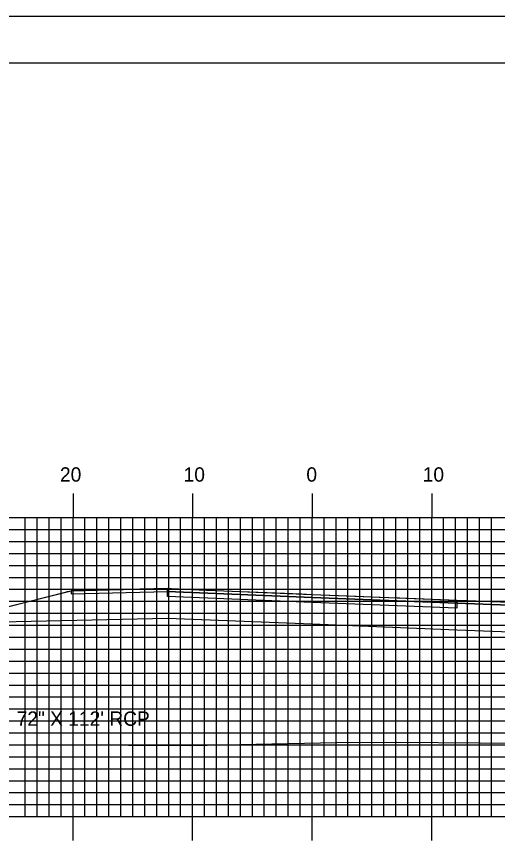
# Model space of a CAD drawing. Extents: x 1814915 to 1815259, y 442591 to 442811.
# Drawn here: x 1815056.3 to 1815096.5, y 442741.2 to 442810.5 of the extents above; entities that cross this region are included whole.
import ezdxf

# ---------------------------------------------------------------- set-up
doc = ezdxf.new("R2010")
doc.units = 0
for name, color, linetype in [('BORDER', 7, 'Continuous'), ('D_Drainage_Culvert', 7, 'Continuous'), ('D_Drainage_Text', 7, 'Continuous'), ('D_Roadway_Centerline', 7, 'Continuous'), ('D_Roadway_Edge_Shoulder', 7, 'Continuous'), ('D_Roadway_Edge_TW', 7, 'Continuous'), ('D_Roadway_Pavement', 7, 'Continuous'), ('D_Roadway_SubGrade', 7, 'Continuous'), ('H_V ANNOTATION', 7, 'Continuous'), ('MAJOR', 7, 'Continuous'), ('MINOR', 7, 'Continuous'), ('PLOT BOUNDARY', 7, 'Continuous'), ('S_Roadway_Centerline', 7, 'Continuous')]:
    doc.layers.add(name, color=color, linetype=linetype)

msp = doc.modelspace()

# ---------------------------------------------------------------- linework, layer by layer
at = {"layer": 'BORDER'}
msp.add_lwpolyline([(1814931.421, 442596.665), (1815251.421, 442596.665), (1815251.421, 442806.665), (1814931.421, 442806.665)], close=True, dxfattribs=at)
at = {"layer": 'D_Drainage_Culvert'}
for p, q in [((1815023.546, 442754.665), (1815135.546, 442754.665)), ((1815023.546, 442748.665), (1815135.546, 442748.665))]:
    msp.add_line(p, q, dxfattribs=at)
at = {"layer": 'D_Roadway_Centerline'}
msp.add_lwpolyline([(1815055.775, 442761.27), (1815057.309, 442761.655), (1815060.475, 442762.45), (1815060.571, 442762.475), (1815060.867, 442762.549), (1815063.058, 442762.599), (1815064.017, 442762.621), (1815068.928, 442762.734), (1815069.264, 442762.72), (1815071.561, 442762.625), (1815072.196, 442762.599), (1815075.06, 442762.482), (1815077.982, 442762.364), (1815080.142, 442762.277), (1815080.312, 442762.27), (1815080.556, 442762.26), (1815081.021, 442762.242), (1815084.712, 442762.094), (1815086.628, 442762.019), (1815087.446, 442761.986), (1815088.366, 442761.95), (1815093.114, 442761.764), (1815096.36, 442761.639), (1815101.177, 442761.455)], dxfattribs=at)
at = {"layer": 'D_Roadway_Edge_Shoulder'}
for points in [[(1815068.928, 442762.734), (1815060.867, 442762.549), (1815060.867, 442762.299), (1815068.928, 442762.484)], [(1815093.114, 442761.764), (1815101.177, 442761.455), (1815101.177, 442761.205), (1815093.114, 442761.514)]]:
    msp.add_lwpolyline(points, close=True, dxfattribs=at)
at = {"layer": 'D_Roadway_Edge_TW'}
msp.add_lwpolyline([(1815068.928, 442762.484), (1815068.928, 442762.734), (1815081.021, 442762.242), (1815093.114, 442761.764), (1815093.114, 442761.514), (1815081.021, 442761.992)], close=True, dxfattribs=at)
at = {"layer": 'D_Roadway_Pavement'}
msp.add_lwpolyline([(1815068.928, 442762.067), (1815068.928, 442762.484), (1815081.021, 442761.992), (1815093.114, 442761.514), (1815093.114, 442761.098), (1815081.021, 442761.575)], close=True, dxfattribs=at)
at = {"layer": 'D_Roadway_SubGrade'}
msp.add_lwpolyline([(1815068.928, 442760.234), (1815049.915, 442759.798), (1815060.867, 442762.549), (1815060.867, 442762.299), (1815068.928, 442762.484), (1815081.021, 442761.992), (1815093.114, 442761.514), (1815101.177, 442761.205), (1815101.177, 442761.455), (1815113.323, 442758.5), (1815093.114, 442759.264), (1815081.021, 442759.742)], close=True, dxfattribs=at)
at = {"layer": 'MAJOR'}
for p, q in [((1815061.021, 442770.669), (1815061.021, 442768.665)), ((1815071.021, 442770.669), (1815071.021, 442768.665)), ((1815081.021, 442770.669), (1815081.021, 442768.665)), ((1815091.021, 442770.669), (1815091.021, 442768.665)), ((1814941.021, 442768.665), (1815221.021, 442768.665)), ((1814941.021, 442768.665), (1815221.021, 442768.665)), ((1815061.021, 442743.665), (1815061.021, 442768.665)), ((1815071.021, 442743.665), (1815071.021, 442768.665)), ((1815081.021, 442743.665), (1815081.021, 442768.665)), ((1815091.021, 442743.665), (1815091.021, 442768.665)), ((1814941.021, 442763.665), (1815221.021, 442763.665)), ((1814941.021, 442758.665), (1815221.021, 442758.665)), ((1814941.021, 442753.665), (1815221.021, 442753.665)), ((1814941.021, 442748.665), (1815221.021, 442748.665)), ((1814941.021, 442743.665), (1815221.021, 442743.665)), ((1814941.021, 442743.665), (1815221.021, 442743.665)), ((1815061.021, 442741.661), (1815061.021, 442743.665)), ((1815071.021, 442741.661), (1815071.021, 442743.665)), ((1815081.021, 442741.661), (1815081.021, 442743.665)), ((1815091.021, 442741.661), (1815091.021, 442743.665))]:
    msp.add_line(p, q, dxfattribs=at)
at = {"layer": 'MINOR'}
for p, q in [((1815057.021, 442743.665), (1815057.021, 442768.665)), ((1815058.021, 442743.665), (1815058.021, 442768.665)), ((1815059.021, 442743.665), (1815059.021, 442768.665)), ((1815060.021, 442743.665), (1815060.021, 442768.665)), ((1815062.021, 442743.665), (1815062.021, 442768.665)), ((1815063.021, 442743.665), (1815063.021, 442768.665)), ((1815064.021, 442743.665), (1815064.021, 442768.665)), ((1815065.021, 442743.665), (1815065.021, 442768.665)), ((1815066.021, 442743.665), (1815066.021, 442768.665)), ((1815067.021, 442743.665), (1815067.021, 442768.665)), ((1815068.021, 442743.665), (1815068.021, 442768.665)), ((1815069.021, 442743.665), (1815069.021, 442768.665)), ((1815070.021, 442743.665), (1815070.021, 442768.665)), ((1815072.021, 442743.665), (1815072.021, 442768.665)), ((1815073.021, 442743.665), (1815073.021, 442768.665)), ((1815074.021, 442743.665), (1815074.021, 442768.665)), ((1815075.021, 442743.665), (1815075.021, 442768.665)), ((1815076.021, 442743.665), (1815076.021, 442768.665)), ((1815077.021, 442743.665), (1815077.021, 442768.665)), ((1815078.021, 442743.665), (1815078.021, 442768.665)), ((1815079.021, 442743.665), (1815079.021, 442768.665)), ((1815080.021, 442743.665), (1815080.021, 442768.665)), ((1815082.021, 442743.665), (1815082.021, 442768.665)), ((1815083.021, 442743.665), (1815083.021, 442768.665)), ((1815084.021, 442743.665), (1815084.021, 442768.665)), ((1815085.021, 442743.665), (1815085.021, 442768.665)), ((1815086.021, 442743.665), (1815086.021, 442768.665)), ((1815087.021, 442743.665), (1815087.021, 442768.665)), ((1815088.021, 442743.665), (1815088.021, 442768.665)), ((1815089.021, 442743.665), (1815089.021, 442768.665)), ((1815090.021, 442743.665), (1815090.021, 442768.665)), ((1815092.021, 442743.665), (1815092.021, 442768.665)), ((1815093.021, 442743.665), (1815093.021, 442768.665)), ((1815094.021, 442743.665), (1815094.021, 442768.665)), ((1815095.021, 442743.665), (1815095.021, 442768.665)), ((1815096.021, 442743.665), (1815096.021, 442768.665)), ((1814941.021, 442767.665), (1815221.021, 442767.665)), ((1814941.021, 442766.665), (1815221.021, 442766.665)), ((1814941.021, 442765.665), (1815221.021, 442765.665)), ((1814941.021, 442764.665), (1815221.021, 442764.665)), ((1814941.021, 442762.665), (1815221.021, 442762.665)), ((1814941.021, 442761.665), (1815221.021, 442761.665)), ((1814941.021, 442760.665), (1815221.021, 442760.665)), ((1814941.021, 442759.665), (1815221.021, 442759.665)), ((1814941.021, 442757.665), (1815221.021, 442757.665)), ((1814941.021, 442756.665), (1815221.021, 442756.665)), ((1814941.021, 442755.665), (1815221.021, 442755.665)), ((1814941.021, 442754.665), (1815221.021, 442754.665)), ((1814941.021, 442752.665), (1815221.021, 442752.665)), ((1814941.021, 442751.665), (1815221.021, 442751.665)), ((1814941.021, 442750.665), (1815221.021, 442750.665)), ((1814941.021, 442749.665), (1815221.021, 442749.665)), ((1814941.021, 442747.665), (1815221.021, 442747.665)), ((1814941.021, 442746.665), (1815221.021, 442746.665)), ((1814941.021, 442745.665), (1815221.021, 442745.665)), ((1814941.021, 442744.665), (1815221.021, 442744.665))]:
    msp.add_line(p, q, dxfattribs=at)
at = {"layer": 'PLOT BOUNDARY'}
msp.add_lwpolyline([(1814915.234, 442590.547), (1815255.234, 442590.547), (1815255.234, 442810.547), (1814915.234, 442810.547)], close=True, dxfattribs=at)
at = {"layer": 'S_Roadway_Centerline'}
msp.add_lwpolyline([(1815005.992, 442749.908), (1815018.998, 442749.725), (1815021.668, 442749.599), (1815038.193, 442749.577), (1815038.357, 442749.576), (1815038.485, 442749.576), (1815040.318, 442749.591), (1815054.077, 442749.699), (1815055.256, 442749.702), (1815070.887, 442749.599), (1815083.088, 442749.849), (1815088.074, 442749.897), (1815095.082, 442749.831), (1815112.583, 442749.662), (1815120.304, 442749.652), (1815126.402, 442749.71), (1815137.574, 442749.683)], dxfattribs=at)

# ---------------------------------------------------------------- texts
at = {"layer": 'D_Drainage_Text'}
msp.add_text('72" X 112\' RCP', height=1.2, dxfattribs=at).set_placement((1815056.306, 442751.256))
at = {"layer": 'H_V ANNOTATION'}
for s, p in [('20', (1815059.929, 442771.665)), ('10', (1815070.271, 442771.665)), ('0', (1815080.539, 442771.665)), ('10', (1815090.271, 442771.665))]:
    msp.add_text(s, height=1.2, dxfattribs=at).set_placement(p)

doc.saveas('drawing.dxf')
